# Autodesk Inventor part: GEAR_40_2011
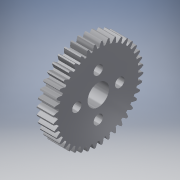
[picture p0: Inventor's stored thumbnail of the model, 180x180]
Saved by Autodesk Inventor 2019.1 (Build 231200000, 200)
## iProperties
Created: 2011-09
Part Number: GEAR_40_2011
Document SubType Name: Modeling
Designer: jagalloro
Density: 1 g/cm^3
Material: Aluminum 6061
Appearance: Aluminum - Flat
Translation Standard: STEP AP203
FileName: GEAR_40_2011
PreProcessor: PRO/ENGINEER BY PARAMETRIC TECHNOLOGY CORPORATION, 2010480
PostProcessor: Build: 239, Release: 2011 RTM - Date: Wed 02/17/2010
Sent Units: millimeter
Uncertainty: 0.004782251495415999
Author: jagalloro
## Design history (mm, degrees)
feature "Base1"
node "GEAR_40_2011"
other parameters: "d0" = 0, "d1" = 0
